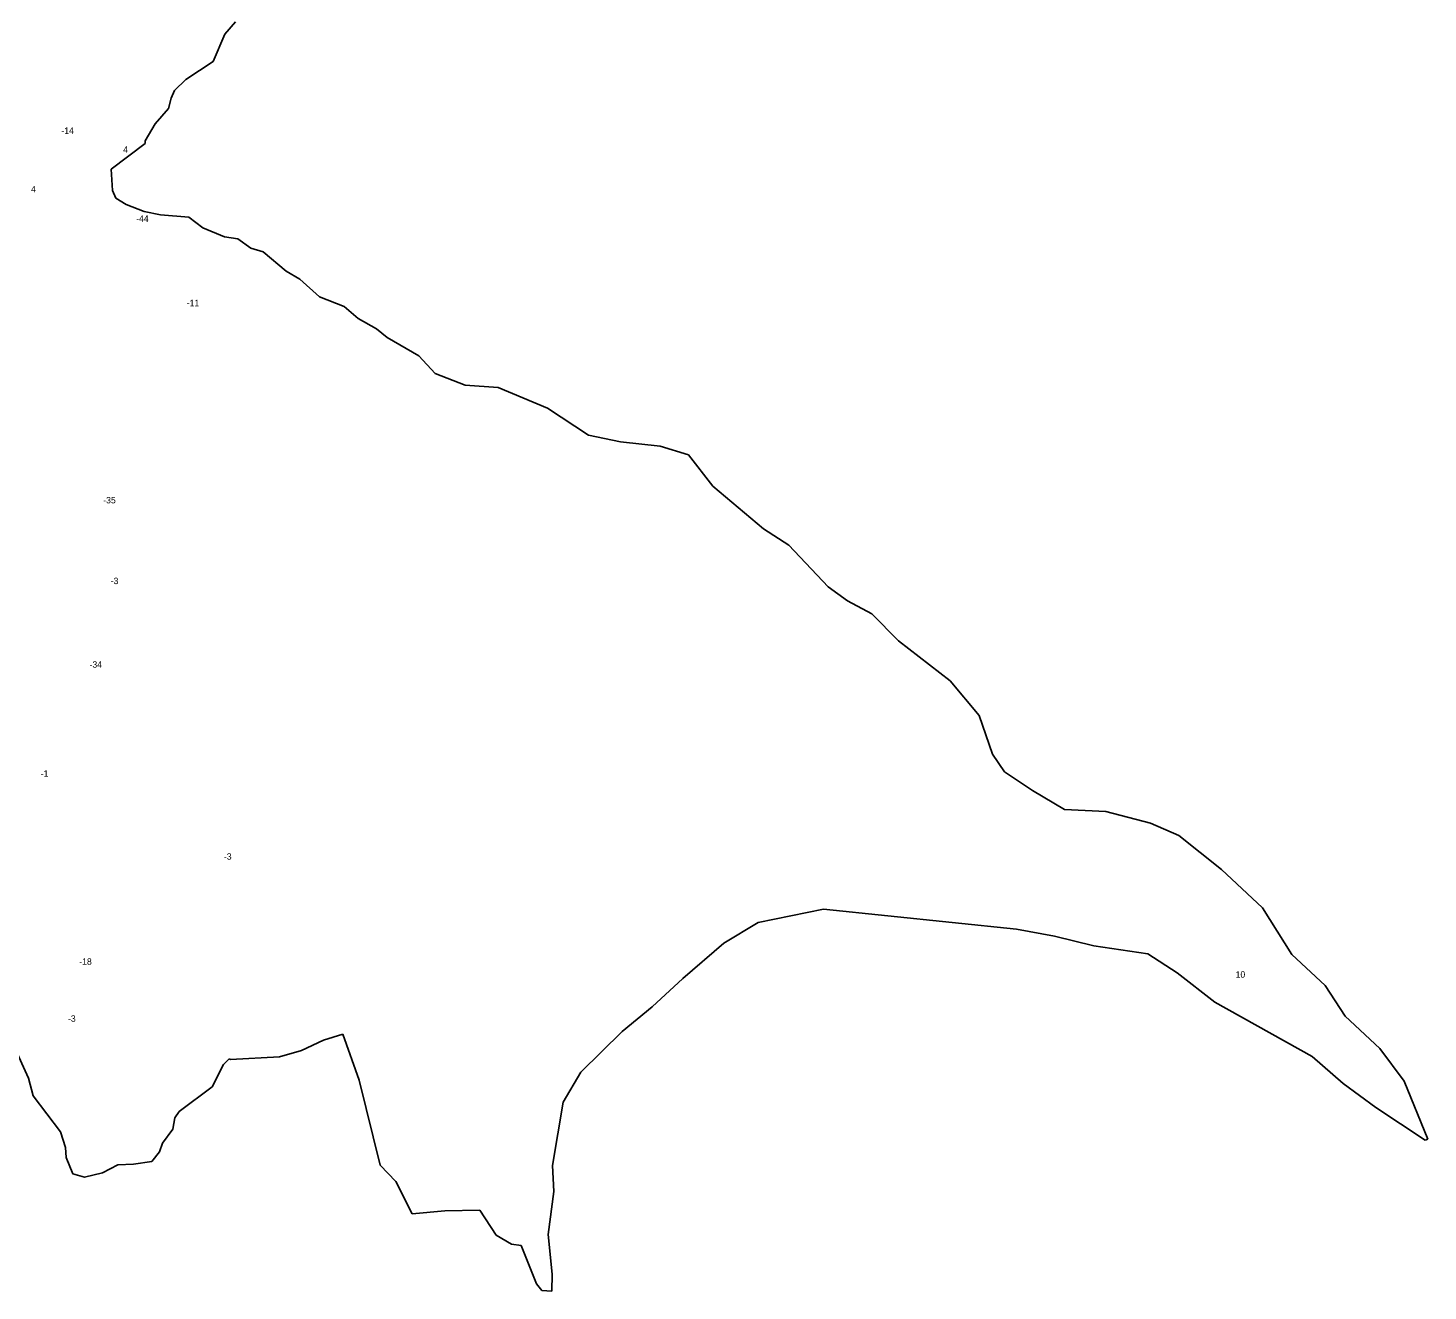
# Model space of a CAD drawing. Extents: x -790002 to -785628, y -971900 to -967971.
# Drawn here: x -787802 to -785628, y -971900 to -969938 of the extents above; entities that cross this region are included whole.
import ezdxf

# ---------------------------------------------------------------- set-up
doc = ezdxf.new("R2010")
doc.units = 0
doc.layers.add('Vrstva 13', color=7, linetype='Continuous')
doc.layers.add('Vrstva 15', color=7, linetype='Continuous')

msp = doc.modelspace()

# ---------------------------------------------------------------- linework, layer by layer
at = {"layer": 'Vrstva 13'}
for p, q in [((-787479.5, -969928.9), (-787496.11, -969948.07)), ((-787496.11, -969948.07), (-787514, -969990.72)), ((-787514, -969990.72), (-787556.47, -970018.52)), ((-787556.47, -970018.52), (-787574.52, -970035.61)), ((-787579.63, -970047.43), (-787583.78, -970063.72)), ((-787574.52, -970035.61), (-787579.63, -970047.43)), ((-787583.78, -970063.72), (-787604.54, -970087.52)), ((-787604.54, -970087.52), (-787619.56, -970113.56)), ((-787619.56, -970113.56), (-787619.56, -970117.71)), ((-787619.56, -970117.71), (-787672.49, -970157.81)), ((-787672.49, -970157.81), (-787670.57, -970190.72)), ((-787670.57, -970190.72), (-787665.46, -970202.54)), ((-787665.46, -970202.54), (-787649.18, -970212.76)), ((-787649.18, -970212.76), (-787621.39, -970223.3)), ((-787621.39, -970223.3), (-787595.84, -970228.73)), ((-787595.84, -970228.73), (-787552.09, -970232.25)), ((-787552.09, -970232.25), (-787530.06, -970248.87)), ((-787530.06, -970248.87), (-787496.52, -970262.92)), ((-787496.52, -970262.92), (-787476.09, -970266.12)), ((-787476.09, -970266.12), (-787455.65, -970280.49)), ((-787455.65, -970280.49), (-787436.8, -970286.25)), ((-787436.8, -970286.25), (-787401.04, -970315.96)), ((-787401.04, -970315.96), (-787379.64, -970328.74)), ((-787379.64, -970328.74), (-787349.31, -970355.89)), ((-787349.31, -970355.89), (-787310.67, -970370.91)), ((-787310.67, -970370.91), (-787289.27, -970389.44)), ((-787289.27, -970389.44), (-787260.85, -970405.73)), ((-787260.85, -970405.73), (-787244.24, -970419.15)), ((-787244.24, -970419.15), (-787194.74, -970447.58)), ((-787194.74, -970447.58), (-787169.83, -970475.06)), ((-787169.83, -970475.06), (-787123.21, -970493.27)), ((-787123.21, -970493.27), (-787071.79, -970496.78)), ((-787071.79, -970496.78), (-786995.14, -970529.04)), ((-786995.14, -970529.04), (-786931.27, -970570.89)), ((-786931.27, -970570.89), (-786882.09, -970581.44)), ((-786882.09, -970581.44), (-786820.14, -970587.83)), ((-786820.14, -970587.83), (-786776.07, -970601.57)), ((-786776.07, -970601.57), (-786738.7, -970650.13)), ((-786738.7, -970650.13), (-786659.82, -970716.58)), ((-786659.82, -970716.58), (-786620.53, -970741.49)), ((-786620.53, -970741.49), (-786559.53, -970806.67)), ((-786559.53, -970806.67), (-786529.51, -970828.07)), ((-786529.51, -970828.07), (-786491.51, -970848.2)), ((-786491.51, -970848.2), (-786450.31, -970890.37)), ((-786450.31, -970890.37), (-786369.83, -970952.35)), ((-786369.83, -970952.35), (-786324.81, -971006.02)), ((-786324.81, -971006.02), (-786304.05, -971066.4)), ((-786304.05, -971066.4), (-786285.53, -971093.55)), ((-786285.53, -971093.55), (-786242.1, -971122.95)), ((-786242.1, -971122.95), (-786192.28, -971152.02)), ((-786192.28, -971152.02), (-786128.41, -971155.54)), ((-786128.41, -971155.54), (-786059.11, -971173.43)), ((-786059.11, -971173.43), (-786015.04, -971192.6)), ((-786015.04, -971192.6), (-785948.61, -971245.63)), ((-785948.61, -971245.63), (-785885.06, -971304.73)), ((-786566.73, -971307.29), (-786667.97, -971327.73)), ((-786267.17, -971338.27), (-786566.73, -971307.29)), ((-785885.06, -971304.73), (-785839.71, -971377.25)), ((-786667.97, -971327.73), (-786721.3, -971359.68)), ((-786208.09, -971349.13), (-786267.17, -971338.27)), ((-786146.77, -971363.83), (-786208.09, -971349.13)), ((-786721.3, -971359.68), (-786785.17, -971414.63)), ((-786063.1, -971376.61), (-786146.77, -971363.83)), ((-786017.43, -971405.68), (-786063.1, -971376.61)), ((-785839.71, -971377.25), (-785787.66, -971425.81)), ((-786785.17, -971414.63), (-786832.44, -971458.72)), ((-785959.31, -971451.36), (-786017.43, -971405.68)), ((-785787.66, -971425.81), (-785757, -971473.41)), ((-786832.44, -971458.72), (-786879.38, -971497.06)), ((-785807.94, -971535.71), (-785959.31, -971451.36)), ((-785757, -971473.41), (-785702.87, -971523.57)), ((-787312.84, -971500.95), (-787342.93, -971510.29)), ((-787287.68, -971572.57), (-787312.84, -971500.95)), ((-786879.38, -971497.06), (-786943.25, -971560)), ((-787801.06, -971569.46), (-787823.63, -971519.37)), ((-787377.17, -971526.38), (-787411.42, -971536.25)), ((-787342.93, -971510.29), (-787377.17, -971526.38)), ((-785702.87, -971523.57), (-785665.27, -971574.21)), ((-787498.07, -971548.18), (-787515.71, -971583.21)), ((-787489.51, -971539.35), (-787498.07, -971548.18)), ((-787487.17, -971540.65), (-787489.51, -971539.35)), ((-787411.42, -971536.25), (-787487.17, -971540.65)), ((-785760.03, -971577.56), (-785807.94, -971535.71)), ((-787793.8, -971596.71), (-787801.06, -971569.46)), ((-786943.25, -971560), (-786970.72, -971606.64)), ((-787515.71, -971583.21), (-787567.07, -971621.11)), ((-787254.73, -971704.41), (-787287.68, -971572.57)), ((-785708.94, -971614.94), (-785760.03, -971577.56)), ((-785665.27, -971574.21), (-785628.14, -971664.46)), ((-787751.52, -971653.02), (-787793.8, -971596.71)), ((-786970.72, -971606.64), (-786987.65, -971705.04)), ((-787573.55, -971631.23), (-787576.92, -971648.87)), ((-787567.07, -971621.11), (-787573.55, -971631.23)), ((-785632.61, -971665.74), (-785708.94, -971614.94)), ((-787743.73, -971677.16), (-787751.52, -971653.02)), ((-787576.92, -971648.87), (-787592.75, -971670.41)), ((-787742.44, -971692.73), (-787743.73, -971677.16)), ((-787592.75, -971670.41), (-787597.42, -971684.17)), ((-785628.14, -971664.46), (-785632.61, -971665.74)), ((-787732.06, -971717.9), (-787742.44, -971692.73)), ((-787609.35, -971698.7), (-787638.15, -971702.85)), ((-787597.42, -971684.17), (-787609.35, -971698.7)), ((-787714.16, -971723.09), (-787732.06, -971717.9)), ((-787686.14, -971716.34), (-787714.16, -971723.09)), ((-787662.01, -971703.89), (-787686.14, -971716.34)), ((-787638.15, -971702.85), (-787662.01, -971703.89)), ((-787230.88, -971730.11), (-787254.73, -971704.41)), ((-786987.65, -971705.04), (-786985.41, -971745.3)), ((-787205.46, -971780.19), (-787230.88, -971730.11)), ((-786985.41, -971745.3), (-786994.04, -971812.07)), ((-787154.35, -971775.78), (-787205.46, -971780.19)), ((-787100.14, -971774.74), (-787154.35, -971775.78)), ((-787074.97, -971813.41), (-787100.14, -971774.74)), ((-787050.85, -971827.17), (-787074.97, -971813.41)), ((-787035.8, -971829.24), (-787050.85, -971827.17)), ((-787012.19, -971888.67), (-787035.8, -971829.24)), ((-786994.04, -971812.07), (-786987.97, -971874.05)), ((-786987.97, -971874.05), (-786988.59, -971900.07)), ((-787004.15, -971899.05), (-787012.19, -971888.67)), ((-786988.59, -971900.07), (-787004.15, -971899.05))]:
    msp.add_line(p, q, dxfattribs=at)

# ---------------------------------------------------------------- texts
at = {"layer": 'Vrstva 15'}
for s, p in [('-14', (-787749.91, -970102.94)), ('4', (-787653.922, -970132.22)), ('4', (-787796.942, -970193.83)), ('-44', (-787633.832, -970239.63)), ('-11', (-787555.319, -970370.63)), ('-35', (-787684.86, -970676.84)), ('-3', (-787673.26, -970802.18)), ('-34', (-787706.146, -970932.03)), ('-1', (-787781.934, -971101.4)), ('-3', (-787497.49, -971230.21)), ('-18', (-787722.094, -971393.34)), ('10', (-785926.811, -971413.47)), ('-3', (-787739.55, -971481.89))]:
    msp.add_text(s, height=10, dxfattribs=at).set_placement(p)

doc.saveas('drawing.dxf')
